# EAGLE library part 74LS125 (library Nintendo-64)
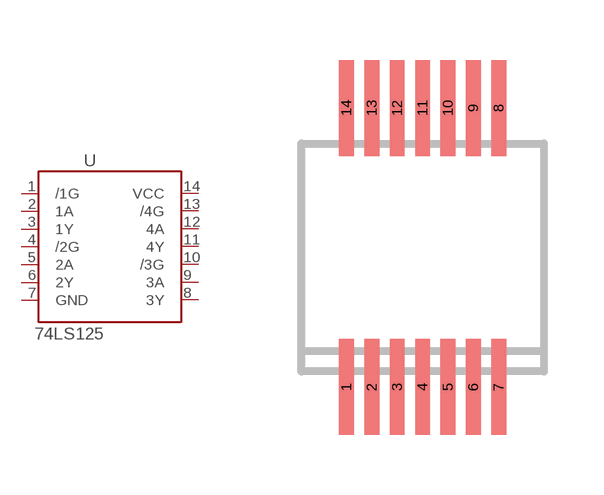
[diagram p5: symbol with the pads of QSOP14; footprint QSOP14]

Designator prefix -

## 74LS125J  [QSOP14]
1  /1G  in
2  1A  in
3  1Y  out
4  /2G  in
5  2A  in
6  2Y  out
7  GND  pwr
8  3Y  out
9  3A  in
10  /3G  in
11  4Y  out
12  4A  in
13  /4G  in
14  VCC  pwr

## Footprint QSOP14 (pad centres in mm)
smd 0.37 x 2.4: 1 -1.905,-3.56; 2 -1.27,-3.56; 3 -0.635,-3.56; 4 0,-3.56; 5 0.635,-3.56; 6 1.27,-3.56; 7 1.905,-3.56; 8 1.905,3.425; 9 1.27,3.425; 10 0.635,3.425; 11 0,3.425; 12 -0.635,3.425; 13 -1.27,3.425; 14 -1.905,3.425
